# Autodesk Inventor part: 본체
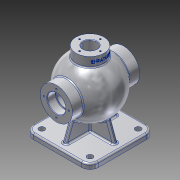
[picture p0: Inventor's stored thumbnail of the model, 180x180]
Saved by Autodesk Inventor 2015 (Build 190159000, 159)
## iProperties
Created: 2025-08
Part Number: 본체
Material: 알루미늄 6061
Document SubType Name: Modeling
Designer: user
Density: 2.7 g/cm^3
Appearance: 알루미늄 - 평지
Mass: 1526.72 g
Surface Area: 1173.82 cm^2
Volume: 565.453 cm^3
Author: user
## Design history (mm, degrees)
sketch "스케치1"
  geometry: L1 (65, 0)-(65, 31); L2 (-65, 31)-(-65, 0); L3 (-65, -31)-(65, 31); L4 (65, -31)-(-65, 31); L5 (65, 31)-(44.215, 31); L6 (-44.215, 31)-(-65, 31); L7 (-65, 0)-(-44, 0); L8 (44, 0)-(65, 0); A1 r 54 centre (0, 0) between (44.215, 31) and (-44.215, 31); A2 r 44 centre (0, 0) between (44, 0) and (-44, 0); 1 further point
  constraints: 16 end point, 4 point on circle, 2 centre point, 2 coincident, 2 midpoint, 2 parallel, 1 horizontal, 1 vertical
  dimensions: "d0" = 108 diameter of A1; "d1" = 130 distance of L1.end L2.start; "d2" = 62 distance of L4.start L1.end; "d3" = 88 diameter of A2; "d4" = 90 deg angle of L1 L5; "d5" = 90 deg angle of L1 L8; "d6" = 64.5024 deg angle of L1 L4; "d7" = 64.5024 deg angle of L1 L3; "d8" = 130 distance between parallel lines of L1 L2; "d9" = 31 distance between parallel lines of L7 L6; "d10" = 0 distance from line of point (0, 0) L8; "d11" = 130 distance from line of L3.start L1
revolve "회전1" sketch "스케치1" stored, may be unused: angle "d12" = 90 deg
hole "구멍1" diameter "d15" = 30; stored, may be unused: countersink angle "d19" = 90 deg, drill point angle "d21" = 118 deg; dims "d13" = 10, "d14" = 10, "d16" = 6, "d17" = 35, "d18" = 16, "d20" = 8
node "작업 평면1"
sketch "스케치2"
  geometry: L1 (62.5, -62.5)-(-62.5, -62.5); L2 (-62.5, -62.5)-(-62.5, 62.5); L3 (-62.5, 62.5)-(62.5, 62.5); L4 (62.5, 62.5)-(62.5, -62.5); L5 (62.5, -62.5)-(-62.5, 62.5); L6 (-62.5, -62.5)-(62.5, 62.5); 1 further point
  constraints: 12 end point, 2 midpoint, 2 parallel, 1 horizontal, 1 perpendicular
  dimensions: "d23" = 125 distance of L2.end L3.end; "d24" = 125 distance of L1.end L2.end
extrude "돌출1" join sketch "스케치2" distance "d25" = 10; taper "d26" = 0 deg
sketch "스케치3"
  geometry: L1 (4, -50.5)-(-4, -50.5); L2 (-4, -50.5)-(-4, 50.5); L3 (-4, 50.5)-(4, 50.5); L4 (4, 50.5)-(4, -50.5); L5 (4, -50.5)-(-4, 50.5); L6 (-4, -50.5)-(4, 50.5); L7 (50.5, -4)-(-50.5, -4); L8 (-50.5, -4)-(-50.5, 4); L9 (-50.5, 4)-(50.5, 4); L10 (50.5, 4)-(50.5, -4); L11 (50.5, -4)-(-50.5, 4); L12 (-50.5, -4)-(50.5, 4); L13 (62.5, -62.5)-(-62.5, -62.5) reference; L14 (-62.5, -62.5)-(-62.5, 62.5) reference; 1 further point
  constraints: 24 end point, 4 midpoint, 4 parallel, 2 horizontal, 2 perpendicular
  dimensions: "d27" = 12 distance between parallel lines of L1 L13; "d28" = 12 distance between parallel lines of L14 L8; "d29" = 8 distance of L7.end L8.end; "d30" = 8 distance of L2.end L3.end
extrude "돌출2" join sketch "스케치3" stored distance "d31" = 10; taper "d32" = 0 deg
feature "면 기울기1" dims angle "d33" = 20 deg
feature "면 기울기2" dims angle "d34" = 20 deg
fillet "모깎기1" dims "d35" = 16
hole "구멍2" diameter "d38" = 11; stored, may be unused: countersink angle "d42" = 90 deg, drill point angle "d44" = 118 deg; dims "d36" = 10, "d37" = 10, "d39" = 6, "d40" = 35, "d41" = 16, "d43" = 8
hole "구멍3" diameter "d47" = 11; stored, may be unused: countersink angle "d51" = 90 deg, drill point angle "d53" = 118 deg; dims "d45" = 10, "d46" = 10, "d48" = 6, "d49" = 35, "d50" = 16, "d52" = 8
hole "구멍4" diameter "d56" = 11; stored, may be unused: countersink angle "d60" = 90 deg, drill point angle "d62" = 118 deg; dims "d54" = 10, "d55" = 10, "d57" = 6, "d58" = 35, "d59" = 16, "d61" = 8
hole "구멍5" diameter "d65" = 11; stored, may be unused: countersink angle "d69" = 90 deg, drill point angle "d71" = 118 deg; dims "d63" = 10, "d64" = 10, "d66" = 6, "d67" = 35, "d68" = 16, "d70" = 8
sketch "스케치4"
  geometry: L1 (0, 0)-(0, 24)
  constraints: 2 end point, 1 vertical
  dimensions: "d72" = 24 distance of L1.start L1.end
hole "구멍6" sketch "스케치4" at (0, 24) diameter "d73" = 3.242; stored, may be unused: countersink angle "d77" = 90 deg, drill point angle "d79" = 118 deg; dims "d74" = 12, "d75" = 35, "d76" = 16, "d78" = 15
node "작업 평면2"
sketch "스케치5"
  geometry: C1 r 27 at (0, 0); 1 further point
  constraints: 1 centre point, 1 coincident
  dimensions: "d84" = 54 diameter of C1
extrude "돌출3" join sketch "스케치5" stored distance "d85" = 10; taper "d86" = 0 deg
hole "구멍7" diameter "d89" = 26; stored, may be unused: countersink angle "d93" = 90 deg, drill point angle "d95" = 118 deg; dims "d87" = 10, "d88" = 10, "d90" = 12, "d91" = 35, "d92" = 16, "d94" = 50
sketch "스케치6"
  geometry: L1 (0, 0)-(0, 20)
  constraints: 2 end point, 1 vertical
  dimensions: "d96" = 20 distance of L1.start L1.end
hole "구멍8" sketch "스케치6" at (0, 20) diameter "d97" = 3.242; stored, may be unused: countersink angle "d101" = 90 deg, drill point angle "d103" = 118 deg; dims "d98" = 9, "d99" = 35, "d100" = 16, "d102" = 11
fillet "모깎기2" dims "d107" = 0.6
fillet "모깎기3" dims "d108" = 3
fillet "모깎기4" dims "d109" = 3
fillet "모깎기5" dims "d110" = 3
fillet "모깎기6" dims "d111" = 3
node "작업 평면3"
sketch "스케치7"
  geometry: L1 (-27, 65)-(27, 65) reference; 2 further points
  constraints: 1 vertical alignment, 1 other
  dimensions: "d113" = 9 distance from line of point (0, 56) L1
feature "엠보싱1" sketch "스케치7" dims "d20" = 8, "d114" = 0.5, "d115" = 0
chamfer "모따기1" distance "d116" = 1; stored, may be unused: second distance "d117" = 2, angle "d118" = 45 deg
node "솔리드1"
mirror "대칭1"
pattern_circular "원형 패턴1" dims angle "d81" = 360 deg
mirror "대칭2"
pattern_circular "원형 패턴2" dims angle "d105" = 360 deg
other parameters: "d22" = -85, "d112" = 133.5
